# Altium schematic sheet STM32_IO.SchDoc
size A; SheetNumber: 5; SheetTotal: 5
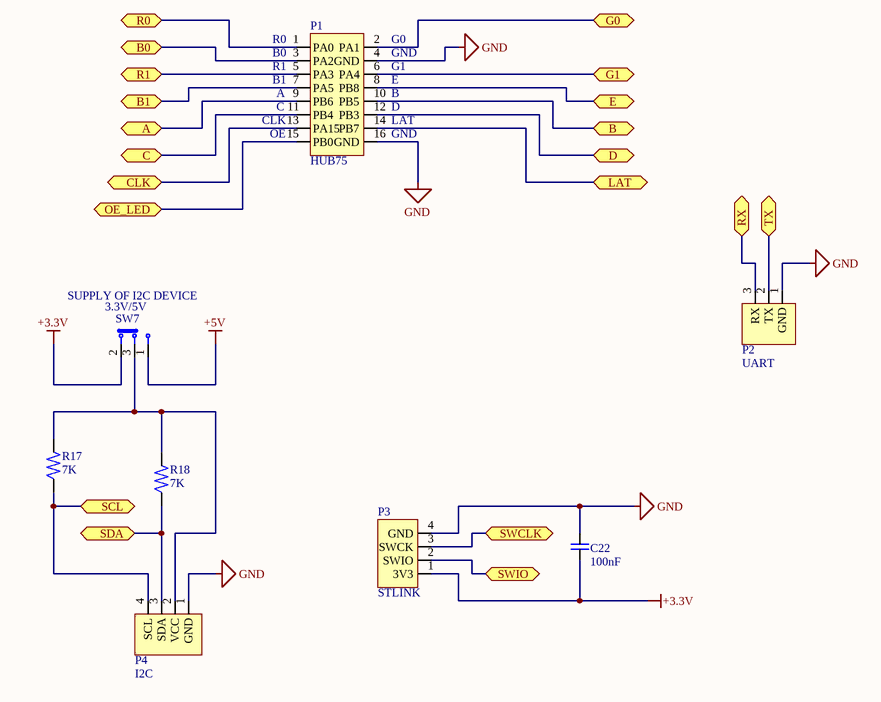
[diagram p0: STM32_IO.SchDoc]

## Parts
C22  100nF  [SMT_CAP_MODEL_1206(3216)_SAMSUNG]
P1  HUB75  [THT_CON_2316S-16G]
P2  UART  [SMT_CON_STRAIGHT_2417SJ-03-SM2]
P3  STLINK  [THT_STLINK_HEADER_4P_MALE]
P4  I2C  [SMT_CON_STRAIGHT_2417SJ-04-SM2]
R17  7K  [SMT_RES_MODEL_1206(3216)_ROHM]
R18  7K  [SMT_RES_MODEL_1206(3216)_ROHM]
SW7  3.3V/5V  [THT_SSW_ESP1010]

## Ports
A (bidir), B0 (bidir), B1 (bidir), B (bidir), C (bidir), CLK (bidir), D (bidir), E (bidir), G0 (bidir), G1 (bidir), LAT (bidir), OE_LED (bidir), R0 (bidir), R1 (bidir), RX (bidir), SCL (bidir), SDA (bidir), SWCLK (bidir), SWIO (bidir), TX (bidir)

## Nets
+3.3V: C22.1 P3.1(3V3) SW7.2
+5V: SW7.1
GND: C22.2 P1.4(GND) P1.16(GND) P2.1(GND) P3.4(GND) P4.1(GND)
A: P1.9(PB6) ; port A
B: P1.10(PB5) ; port B
B0: P1.3(PA2) ; port B0
B1: P1.7(PA5) ; port B1
C: P1.11(PB4) ; port C
CLK: P1.13(PA15) ; port CLK
D: P1.12(PB3) ; port D
E: P1.8(PB8) ; port E
G0: P1.2(PA1) ; port G0
G1: P1.6(PA4) ; port G1
LAT: P1.14(PB7) ; port LAT
OE_LED: P1.15(PB0) ; port OE_LED
R0: P1.1(PA0) ; port R0
R1: P1.5(PA3) ; port R1
RX: P2.3(RX) ; port RX
SCL: P4.4(SCL) R17.2 ; port SCL
SDA: P4.3(SDA) R18.2 ; port SDA
SWCLK: P3.3(SWCK) ; port SWCLK
SWIO: P3.2(SWIO) ; port SWIO
TX: P2.2(TX) ; port TX
NetP4_2: P4.2(VCC) R17.1 R18.1 SW7.3

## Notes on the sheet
- (near P1) R0
- (near P1) B0
- (near P1) R1
- (near P1) B1
- (near P1) G0
- (near P1) GND
- (near P1) G1
- (near P1) E
- (near P1) CLK
- (near P1) OE
- (near P1) A
- (near P1) C
- (near P1) B
- (near P1) D
- (near P1) LAT
- (near SW7) SUPPLY OF I2C DEVICE

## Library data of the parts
C22 = SMT_CAP_MODEL_1206(3216)_SAMSUNG: SMT Samsung Ceramic Capacitor MODEL *V *nF 1206(3216)  CL31B104KBCNNNC(etc.)
P1 = THT_CON_2316S-16G: Connector 2316S-16G 16 Pin 2.54 Pitch
P2 = SMT_CON_STRAIGHT_2417SJ-03-SM2: Connector 3P NELTRON 2417SJ-03-SM2-CR 100V/2A 2.0mm Pitch SMT
P3 = THT_STLINK_HEADER_4P_MALE: Dupont Header Male STLINK 4P 2.54 Pitch
P4 = SMT_CON_STRAIGHT_2417SJ-04-SM2: Connector 4P NELTRON 2417SJ-04-SM2-CR 100V/2A 2.0mm Pitch SMT
R17 R18 = SMT_RES_MODEL_1206(3216)_ROHM: SMT ROHM Resistor MODEL 1206(3216) 1/4W MCR18ERTJ000
SW7 = THT_SSW_ESP1010: Slide Switch ESP1010 12V 0.5A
